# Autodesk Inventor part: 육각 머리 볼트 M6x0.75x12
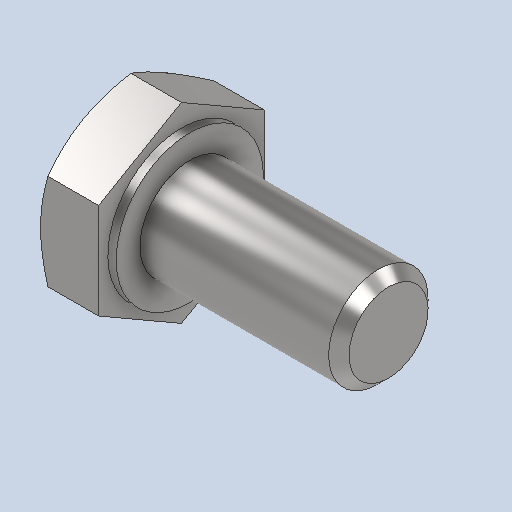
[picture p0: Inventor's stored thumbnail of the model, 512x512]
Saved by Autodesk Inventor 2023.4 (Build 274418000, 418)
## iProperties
Created: 2024-09
Part Number: 육각 머리 볼트 M6x0.75x12
Material: 강철, 연강
Description: 6각 머리 볼트 및 6각 머리 나사
Document SubType Name: Modeling
Designer: EDU
Density: 7.85 g/cm^3
Appearance: 기본값
Author: jhkim
Sending System: Autodesk Inventor 2025
Preprocessor: ST-DEVELOPER v20
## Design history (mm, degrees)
feature "Solid1"
node "솔리드1"
